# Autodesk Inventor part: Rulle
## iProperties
Author: Tobben
Created: 2001-12
Part Number: Rulle
Material: Aluminum-6061
Document SubType Name: Modeling
Designer: Tobben
Control State: 0
Master: False
Checked Out: False
PropertySet Name: Design Tracking Control
Shininess: 64.0
Angle Display Precision: 2
Document Length Units: 11269
Document Angle Units: 11283
Document Time Units: 11279
Document Mass Units: 11290
Document Length Units Precision: 3
Document Angle Units Precision: 2
Compacted: False
PropertySet Name: _Private Model Information
Density: 0.0
Volumn: 0.0
Area: 0.0
PropertySet Name: Model Information
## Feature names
1. Extrusion1
